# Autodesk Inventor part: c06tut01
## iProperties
Shininess: 77.0
Length Units: 11269
Angle Units: 11279
Time Units: 11290
Mass Units: 11283
Length Display Precision: 3
Angle Display Precision: 2
Created: 2002-02
Part Number: c06tut01
Document SubType Name: Modeling
Designer: ***
Density: 0.0
Volumn: 0.0
Area: 0.0
PropertySet Name: Model Information
Control State: 0
Master: False
Checked Out: False
Author: ***
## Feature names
1. Extrusion1
2. Extrusion2
3. Extrusion3
4. Extrusion4
5. Extrusion5
6. Fillet2
7. Extrusion6
8. Hole1
